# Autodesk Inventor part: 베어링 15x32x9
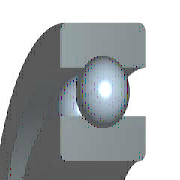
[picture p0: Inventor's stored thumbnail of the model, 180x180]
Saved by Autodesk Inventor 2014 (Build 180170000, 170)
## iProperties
IsCustomPart: 0
Created: 2012-02
Part Number: 베어링 15x32x9
Material: 강철, 연강
Description: 깊은 그루브 볼 베어링
Document SubType Name: Modeling
Standard: KS B 2023
Designer: mduedu
Standards Organization: KS
Language: ko-KR
Size Designation: 6002 - 15 x 32 x 9
Categories: <MemberInstance><Categories><Category DisplayName="샤프트 부품" InternalName="7f7aeb1f-a693-4053-b835-cee3144e0d98" Mnemonic="SHFT"><Category DisplayName="베어링" Inter
Density: 1 g/cm^3
Appearance: 노란색
Author: mduedu
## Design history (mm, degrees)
sketch "스케치" dims "d0" = 4.42 (= -0.26 x WD + 0.26 x BD)
  geometry: L1 (2.29, 11.75)-(6.71, 11.75); L2 (4.5, 11.75)-(4.5, 9.54); L3 (4.5, 11.75)-(4.5, 13.96); L4 (2.858, 10.271)-(0, 10.271); L5 (0, 7.5)-(9, 7.5); L6 (2.858, 13.229)-(0, 13.229); L7 (0, 16)-(9, 16); L8 (9, 7.5)-(9, 10.271); L9 (6.142, 10.271)-(9, 10.271); L10 (6.142, 13.229)-(9, 13.229); L11 (9, 16)-(9, 13.229); L12 (-1.4, 0)-(8.4, 0) reference; L13 (0, -0.3)-(0, 5.3) reference
  constraints: 22 end point, 4 point on line, 2 collinear, 2 perpendicular, 2 symmetric about line, 1 midpoint, 1 parallel, 14 other
  dimensions: "d9" = 15 diameter of L5 L12 (= WD); "d11" = 32 diameter of L7 L12 (= BD); "d12" = 9 distance between parallel lines of L8 L13 (= KB); "d13" = 20.542 diameter of L9 L12 (= 0.326 x BD + 0.674 x WD)
revolve "본체" stored, may be unused: angle "d6" = 90 deg
revolve "볼" stored, may be unused: angle "d7" = 90 deg
pattern_circular "IDS_ARRAYBALL[SIMPL:T]" dims angle "d3" = 360 deg
body "Solid1"
fillet "모깎기1" dims "d1" = 0.3 (= KRS)
other parameters: "WD" = 15 [user parameter; used in 5 equation terms], "BD" = 32 [user parameter; used in 5 equation terms], "KB" = 9 [user parameter; used in 1 equation term], "KRS" = 0.3 [user parameter; used in 1 equation term], "d4" = 0, "d5" = 0, "d8" = 0, "d14" = 0, "d15" = 0, "BBA" = 0 [user parameter], "BC0" = 2850000 [user parameter], "BC" = 5590000 [user parameter], "BR" = 16 (= 0.5 x BD) [user parameter], "WR" = 7.5 (= 0.5 x WD) [user parameter]
